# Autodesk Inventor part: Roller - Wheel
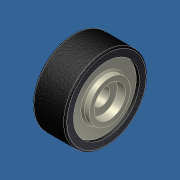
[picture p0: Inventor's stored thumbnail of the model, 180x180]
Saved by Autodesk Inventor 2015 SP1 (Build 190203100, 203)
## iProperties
Category: Mechanical Engineering Drawing and Design - CADD
Manager: Fábio Ricardo de Oliveira Souza
Company: SENAI - Serviço Nacional de Aprendizagem Industrial
Created: 2011-06
Part Number: Roller - Wheel
Material: Steel
Description: Purchased
Document SubType Name: Modeling
Designer: Guilherme Augusto Franco de Souza
Engineer: George Geraldo de Oliveia Silva
Authority: Fábio Ricardo de Oliveira Soza
Density: 7.85 g/cm^3
Mass: 268.857 g
Surface Area: 128.753 cm^2
Volume: 34.2493 cm^3
Appearance: Machined 02
Subject: WorldSkill 2011 - London, England
Author: Guilherme Augusto Franco de Souza
Revision Number: 00
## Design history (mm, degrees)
sketch "Sketch2"
  geometry: L1 (-12, 0)-(12, 0); L2 (12, 0)-(12, 12.5); L3 (12, 12.5)-(8, 12.5); L4 (8, 12.5)-(8, 20); L5 (8, 20)-(10, 20); L6 (10, 20)-(10, 25); L7 (10, 25)-(-10, 25); L8 (-10, 25)-(-10, 20); L9 (-10, 20)-(-8, 20); L10 (-8, 20)-(-8, 12.5); L11 (-8, 12.5)-(-12, 12.5); L12 (-12, 12.5)-(-12, 0); 2 further points
  constraints: 24 end point, 10 parallel, 4 equal length, 1 coincident, 1 horizontal, 1 midpoint, 1 perpendicular
  dimensions: "d2" = 50 diameter of L7 L1; "d3" = 25 diameter of L11 L1; "d4" = 20 distance of L6.end L7.end; "d5" = 24 distance of L1.start L1.end; "d6" = 16 distance between parallel lines of L4 L10; "d7" = 5 distance between parallel lines of L7 L9
revolve "Revolution1" sketch "Sketch2" stored, may be unused: angle "d8" = 90 deg
hole "Hole1" diameter "d11" = 10; stored, may be unused: countersink angle "d15" = 90 deg, drill point angle "d17" = 118 deg; dims "d9" = 10, "d10" = 10, "d12" = 6, "d13" = 4, "d14" = 2, "d16" = 8
fillet "Fillet1" dims "d18" = 1
sketch "Sketch3"
  geometry: C1 r 20 at (0, 0) reference; 1 further point
extrude_surface "ExtrusionSrf1" sketch "Sketch3" dims "d19" = 30, "d20" = 0
split "Split1"
  body "Solid2"
chamfer "Chamfer1" distance "d21" = 1; stored, may be unused: second distance "d22" = 2, angle "d23" = 45 deg
hole "Hole2" diameter "d26" = 19; stored, may be unused: countersink angle "d30" = 90 deg, drill point angle "d32" = 0 deg; dims "d27" = 6, "d28" = 4, "d29" = 2, "d31" = 5, "d42" = 10, "d43" = 10
hole "Hole3" diameter "d35" = 19; stored, may be unused: countersink angle "d39" = 90 deg, drill point angle "d41" = 0 deg; dims "d36" = 6, "d37" = 4, "d38" = 2, "d40" = 5, "d44" = 10, "d45" = 10
body "Srf1"
body "Solid3"
body "Solid4"
